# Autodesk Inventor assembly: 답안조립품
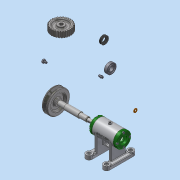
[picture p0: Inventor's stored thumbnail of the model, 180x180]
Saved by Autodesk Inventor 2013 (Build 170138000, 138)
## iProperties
Created: 2015-11
Part Number: 답안조립품
Document SubType Name: Assembly
Designer: ST4
Author: ST4
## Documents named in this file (16)
- C:\Users\ST4\Desktop\451109V1017\답안조립품.iam
- C:\Users\ST4\Desktop\451109V1017\본체.ipt
- C:\Users\ST4\Desktop\451109V1017\V벨트풀리.ipt
- C:\Users\ST4\Desktop\451109V1017\너트 M 8.ipt
- C:\Users\ST4\Desktop\451109V1017\니플 M 6 x 0.75.ipt
- C:\Users\ST4\Desktop\451109V1017\베어링 15 x 32 x 9.ipt
- C:\Users\ST4\Desktop\451109V1017\볼트 M 6 x 8.ipt
- C:\Users\ST4\Desktop\451109V1017\볼트 M4 x 12.ipt
- C:\Users\ST4\Desktop\451109V1017\스퍼기어.ipt
- C:\Users\ST4\Desktop\451109V1017\스프링와셔 8.ipt
- C:\Users\ST4\Desktop\451109V1017\오일 실 15 25 7.ipt
- C:\Users\ST4\Desktop\451109V1017\와셔 6x11.5.ipt
- C:\Users\ST4\Desktop\451109V1017\와셔 8x17.ipt
- C:\Users\ST4\Desktop\451109V1017\축.ipt
- C:\Users\ST4\Desktop\451109V1017\커버.ipt
- C:\Users\ST4\Desktop\451109V1017\키 3 x 3 x 12.ipt
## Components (10 placed, 3 different names)
1. V벨트풀리:1
2. KS B 2023 6002 - 15 x 32 x 9:1
3. ISO 4762 M4 x 12:1
4. ISO 4762 M4 x 12:2
5. ISO 4762 M4 x 12:3
6. ISO 4762 M4 x 12:4
7. ISO 4762 M4 x 12:5
8. ISO 4762 M4 x 12:6
9. ISO 4762 M4 x 12:7
10. ISO 4762 M4 x 12:8
